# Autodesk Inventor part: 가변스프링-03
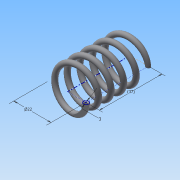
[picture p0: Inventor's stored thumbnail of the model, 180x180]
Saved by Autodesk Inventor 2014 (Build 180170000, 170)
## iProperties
Created: 2015-09
Part Number: 가변스프링-03
Material: 강철, 탄소
Document SubType Name: Modeling
Designer: study
Density: 7.87 g/cm^3
Appearance: 반연마
Mass: 18.7976 g
Surface Area: 32.4648 cm^2
Volume: 2.38851 cm^3
Author: study
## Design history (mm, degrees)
sketch "스케치1"
  geometry: L1 (0, 0)-(11, 0); L2 (11, 0)-(11, 29.043); L3 (11, 29.043)-(0, 29.043); L4 (0, 29.043)-(0, 0); C1 r 1.5 at (11, 0)
  constraints: 8 end point, 2 parallel, 1 centre point, 1 coincident, 1 horizontal, 1 perpendicular
  dimensions: "d0" = 22 diameter of L2 L4; "d1" = 3 diameter of C1; "d2" = 29.04259 distance of L1.end L2.end (derived)
feature "코일1" sketch "스케치1" pitch "d3" = 10; turns "d5" = 5; dims "d4" = 29.04259 (= d2), "d6" = 0, angle "d7" = 90 deg, angle "d8" = 90 deg, "d9" = 0, "d10" = 0
sketch "스케치2"
  geometry: L1 (-12.5, 0)-(-9.5, 0) reference; 1 further point
  constraints: 1 horizontal alignment
extrude "돌출1" cut sketch "스케치2" stored distance "d11" = 10; taper "d12" = 0 deg
node "작업 평면1"
sketch "스케치3"
  geometry: L1 (-9.5, 0)-(-12.5, 0) reference; 1 further point
  constraints: 1 horizontal alignment
extrude "돌출2" cut sketch "스케치3" stored distance "d14" = 10; taper "d15" = 0 deg
node "솔리드1"
node "절단 모서리 투영1"
node "절단 모서리 투영2"
other parameters: "d13" = 29.04259 (= d2)
